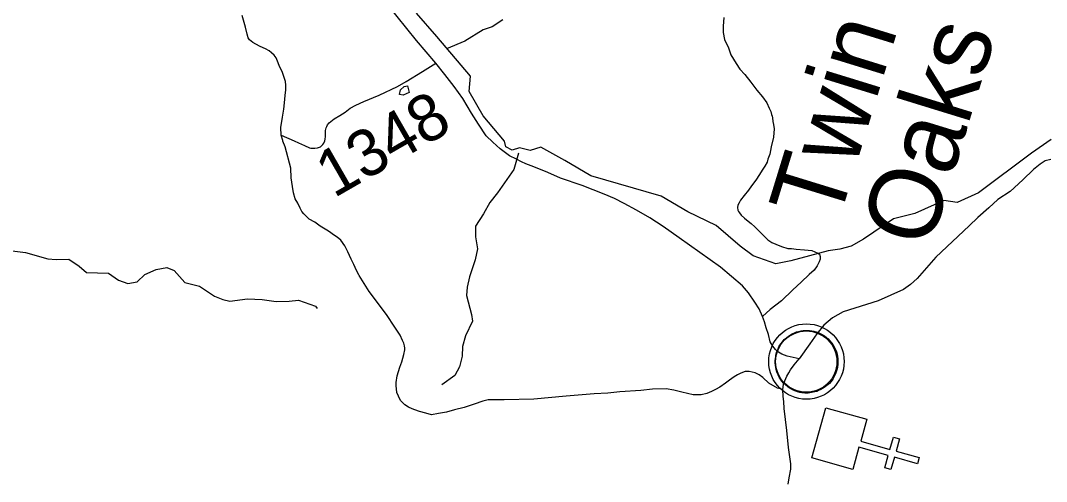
# Model space of a CAD drawing. Extents: x 1347947 to 1350662, y 1027710 to 1030532.
# Drawn here: x 1348247.6 to 1348346.4, y 1029005 to 1029049.4 of the extents above; entities that cross this region are included whole.
import ezdxf

# ---------------------------------------------------------------- set-up
doc = ezdxf.new("R2010")
doc.units = 0
doc.layers.add('Default', color=7, linetype='Continuous')
doc.layers.add('Prop Leader Line Light', color=7, linetype='Continuous')

msp = doc.modelspace()

# ---------------------------------------------------------------- linework, layer by layer
at = {"layer": 'Default'}
for points in [[(1348287.596, 1029045.249), (1348285.737, 1029047.442), (1348282.93, 1029050.893)], [(1348272.718, 1029038.317), (1348272.664, 1029039.067), (1348272.835, 1029040.054), (1348272.962, 1029040.826), (1348273.015, 1029041.423), (1348273.085, 1029042.122), (1348273.143, 1029042.683), (1348273.157, 1029043.125), (1348273.112, 1029043.468), (1348272.84, 1029044.35), (1348272.521, 1029045.015), (1348272.344, 1029045.442), (1348272.213, 1029045.744), (1348272.04, 1029046.009), (1348271.786, 1029046.237), (1348271.543, 1029046.432), (1348271.192, 1029046.629), (1348270.689, 1029046.866), (1348270.253, 1029047.079), (1348269.965, 1029047.242), (1348269.657, 1029047.494), (1348269.539, 1029047.678), (1348269.416, 1029048.026), (1348269.259, 1029048.719), (1348268.952, 1029049.839)], [(1348346.885, 1029037.888), (1348344.993, 1029036.589), (1348339.881, 1029032.765), (1348337.806, 1029031.843), (1348336.544, 1029032.014), (1348333.757, 1029030.782), (1348331.68, 1029030.263), (1348328.8, 1029028.306), (1348327.621, 1029027.63), (1348326.526, 1029027.335), (1348325.385, 1029027.18), (1348321.787, 1029026.211), (1348320.348, 1029025.926), (1348318.162, 1029026.695), (1348316.916, 1029027.631), (1348314.609, 1029029.625), (1348311.88, 1029030.919), (1348309.291, 1029032.455), (1348302.523, 1029034.392), (1348300.036, 1029035.874), (1348297.703, 1029037.164), (1348296.673, 1029036.847), (1348295.653, 1029037.097), (1348294.968, 1029036.872), (1348294.34, 1029037.199), (1348294.219, 1029037.743), (1348292.171, 1029040.162), (1348290.818, 1029042.518), (1348290.93, 1029043.99), (1348287.701, 1029047.804), (1348285.752, 1029050.071)], [(1348294.061, 1029049.412), (1348293.016, 1029048.757), (1348292.153, 1029048.449), (1348290.39, 1029047.373), (1348288.638, 1029046.62)], [(1348315.344, 1029049.632), (1348315.292, 1029048.799), (1348315.269, 1029048.193), (1348315.411, 1029047.533), (1348315.781, 1029046.707), (1348316.028, 1029046.033), (1348316.522, 1029045.213), (1348316.883, 1029044.664), (1348317.363, 1029044.151), (1348317.959, 1029043.409), (1348318.526, 1029042.652), (1348319.064, 1029042.012), (1348319.47, 1029041.424), (1348319.705, 1029040.901), (1348319.859, 1029040.582), (1348319.939, 1029040.289), (1348319.985, 1029040.134), (1348320.033, 1029039.971), (1348320.078, 1029039.629), (1348320.131, 1029039.35), (1348320.179, 1029038.911), (1348320.117, 1029038.135), (1348319.918, 1029037.179), (1348319.767, 1029036.474), (1348319.578, 1029035.996), (1348319.516, 1029035.729), (1348319.296, 1029035.336), (1348319.043, 1029034.956), (1348318.775, 1029034.54), (1348318.433, 1029033.965), (1348318.019, 1029033.45), (1348317.705, 1029033.021), (1348317.309, 1029032.504), (1348316.944, 1029032.058), (1348316.818, 1029031.8), (1348316.705, 1029031.58), (1348316.669, 1029031.342), (1348316.703, 1029031.102), (1348316.761, 1029030.978), (1348316.85, 1029030.825), (1348317.002, 1029030.612), (1348317.326, 1029030.316), (1348317.694, 1029030.024), (1348317.965, 1029029.808), (1348318.338, 1029029.474), (1348318.656, 1029029.159), (1348318.957, 1029028.852), (1348319.287, 1029028.512), (1348319.582, 1029028.246), (1348319.98, 1029027.986), (1348320.367, 1029027.81), (1348320.9, 1029027.584), (1348321.507, 1029027.394), (1348321.848, 1029027.398), (1348322.316, 1029027.345), (1348323.112, 1029027.27), (1348323.813, 1029027.21), (1348324.392, 1029026.96), (1348324.555, 1029026.842), (1348324.612, 1029026.632), (1348324.609, 1029026.365), (1348324.525, 1029026.108), (1348324.337, 1029025.734), (1348324.048, 1029025.309), (1348323.562, 1029024.898), (1348322.778, 1029024.174), (1348321.978, 1029023.414), (1348320.883, 1029022.365), (1348319.821, 1029021.522), (1348319.071, 1029020.842)], [(1348272.718, 1029038.317), (1348273.968, 1029037.778), (1348274.379, 1029037.56), (1348274.935, 1029037.304), (1348275.42, 1029037.09), (1348275.553, 1029037.063), (1348275.711, 1029037.049), (1348275.961, 1029037.064), (1348276.192, 1029037.082), (1348276.314, 1029037.141), (1348276.495, 1029037.203), (1348276.703, 1029037.403), (1348276.813, 1029037.548), (1348276.91, 1029037.765), (1348276.934, 1029037.915), (1348276.965, 1029038.187), (1348276.96, 1029038.529), (1348276.973, 1029038.773), (1348277.034, 1029039.011), (1348277.095, 1029039.148), (1348277.154, 1029039.303), (1348277.337, 1029039.509), (1348277.819, 1029039.892), (1348278.34, 1029040.21), (1348278.861, 1029040.539), (1348279.359, 1029040.916), (1348279.885, 1029041.201), (1348280.657, 1029041.543), (1348282.139, 1029042.17), (1348283.916, 1029042.999), (1348284.756, 1029043.481), (1348286.316, 1029044.436), (1348287.596, 1029045.249)], [(1348319.071, 1029020.842), (1348318.744, 1029021.584), (1348318.321, 1029022.24), (1348317.71, 1029023.142), (1348317.142, 1029023.812), (1348315.021, 1029025.606), (1348311.048, 1029028.418), (1348309.509, 1029029.511), (1348308.226, 1029030.369), (1348306.945, 1029031.093), (1348305.75, 1029031.736), (1348304.797, 1029032.21), (1348303.821, 1029032.645), (1348301.699, 1029033.47), (1348299.614, 1029034.174), (1348298.394, 1029034.713), (1348297.051, 1029035.267), (1348296.276, 1029035.553), (1348295.859, 1029035.759), (1348295.357, 1029036.006), (1348294.7, 1029036.332), (1348293.814, 1029037.007), (1348293.091, 1029037.625), (1348292.457, 1029038.25), (1348291.717, 1029039.383), (1348291.052, 1029040.445), (1348290.186, 1029041.848), (1348289.372, 1029043), (1348288.465, 1029044.163), (1348287.596, 1029045.249)], [(1348285.043, 1029042.412), (1348284.45, 1029042.172), (1348284.103, 1029042.233), (1348284.213, 1029042.663), (1348284.535, 1029042.999), (1348284.859, 1029043.049), (1348285.043, 1029042.412)], [(1348285.043, 1029042.412), (1348284.45, 1029042.172), (1348284.103, 1029042.233), (1348284.213, 1029042.663), (1348284.535, 1029042.999), (1348284.859, 1029043.049), (1348285.043, 1029042.412)], [(1348321.021, 1029013.83), (1348320.503, 1029013.967), (1348319.688, 1029014.434), (1348319.109, 1029014.983), (1348318.751, 1029015.232), (1348318.35, 1029015.429), (1348317.797, 1029015.548), (1348317.413, 1029015.56), (1348316.981, 1029015.402), (1348316.66, 1029015.221), (1348316.329, 1029015.032), (1348315.893, 1029014.713), (1348315.494, 1029014.445), (1348314.946, 1029014.046), (1348314.542, 1029013.818), (1348314.156, 1029013.647), (1348313.697, 1029013.44), (1348313.165, 1029013.319), (1348312.751, 1029013.3), (1348312.393, 1029013.323), (1348311.311, 1029013.557), (1348310.511, 1029013.774), (1348309.801, 1029013.899), (1348308.479, 1029013.849), (1348307.332, 1029013.723), (1348305.337, 1029013.584), (1348304.155, 1029013.471), (1348302.861, 1029013.399), (1348300.155, 1029013.178), (1348297.036, 1029012.897), (1348294.175, 1029012.814), (1348293.083, 1029012.826), (1348292.633, 1029012.82), (1348292.12, 1029012.693), (1348291.307, 1029012.405), (1348290.316, 1029012.078), (1348289.407, 1029011.876), (1348288.644, 1029011.627), (1348287.845, 1029011.498), (1348287.185, 1029011.394), (1348286.64, 1029011.532), (1348286.026, 1029011.701), (1348285.571, 1029011.858), (1348285.307, 1029011.949), (1348284.979, 1029012.114), (1348284.623, 1029012.346), (1348284.232, 1029012.747), (1348284.101, 1029012.955), (1348283.995, 1029013.176), (1348283.853, 1029013.532), (1348283.769, 1029014.209), (1348283.787, 1029014.493), (1348283.878, 1029015.135), (1348284.133, 1029015.982), (1348284.322, 1029016.493), (1348284.516, 1029017.193), (1348284.606, 1029017.629), (1348284.626, 1029017.805), (1348284.596, 1029018.022), (1348284.512, 1029018.273), (1348284.405, 1029018.557), (1348284.168, 1029019.067), (1348283.572, 1029019.927), (1348282.911, 1029020.965), (1348282.08, 1029022.088), (1348281.186, 1029023.263), (1348280.524, 1029024.288), (1348280.21, 1029024.81), (1348280.186, 1029024.853), (1348279.944, 1029025.294), (1348279.716, 1029025.866), (1348279.458, 1029026.374), (1348279.121, 1029027.072), (1348278.843, 1029027.662), (1348278.443, 1029028.209), (1348278.089, 1029028.477), (1348277.848, 1029028.663), (1348277.268, 1029029.078), (1348276.456, 1029029.566), (1348275.95, 1029029.947), (1348275.389, 1029030.237), (1348274.886, 1029030.741), (1348274.693, 1029030.95), (1348274.523, 1029031.287), (1348274.297, 1029031.752), (1348274.065, 1029032.186), (1348273.887, 1029032.759), (1348273.798, 1029033.377), (1348273.679, 1029034.212), (1348273.633, 1029035.14), (1348273.095, 1029037.205), (1348272.878, 1029037.749), (1348272.873, 1029037.792), (1348272.718, 1029038.317)], [(1348295.549, 1029036.593), (1348295.099, 1029035.018), (1348293.537, 1029032.771), (1348292.805, 1029031.845), (1348292.192, 1029030.733), (1348291.406, 1029029.54), (1348291.416, 1029028.518), (1348291.605, 1029027.37), (1348291.4, 1029026.32), (1348290.828, 1029024.685), (1348290.619, 1029023.677), (1348290.546, 1029022.886), (1348291.041, 1029021.04), (1348291.123, 1029020.401), (1348290.469, 1029018.998), (1348290.173, 1029017.98), (1348290.153, 1029017.048), (1348289.894, 1029016.018), (1348289.432, 1029015.16), (1348288.163, 1029014.278)], [(1348346.855, 1029035.975), (1348346.293, 1029035.843), (1348345.804, 1029035.535), (1348345.159, 1029034.992), (1348344.136, 1029034.002), (1348342.938, 1029032.879), (1348341.739, 1029032.13), (1348340.855, 1029031.328), (1348339.798, 1029030.376)], [(1348339.798, 1029030.376), (1348338.973, 1029029.578), (1348335.779, 1029026.566), (1348333.98, 1029024.515), (1348333.315, 1029023.943), (1348332.662, 1029023.454), (1348330.196, 1029022.362), (1348326.822, 1029021.293), (1348325.813, 1029020.731), (1348324.982, 1029020.015), (1348324.295, 1029019.181), (1348323.62, 1029018.206)], [(1348246.283, 1029027.228), (1348248.082, 1029027.005), (1348250.239, 1029026.413), (1348251.03, 1029026.34), (1348252.26, 1029026.358), (1348253.254, 1029025.704), (1348253.957, 1029025.091), (1348256.081, 1029025.041), (1348257.02, 1029024.346), (1348257.929, 1029024.028), (1348258.837, 1029024.178), (1348259.555, 1029024.886), (1348260.646, 1029025.381), (1348261.689, 1029025.566), (1348262.403, 1029025.276), (1348263.433, 1029024.14), (1348264.835, 1029023.772), (1348266.268, 1029022.801), (1348267.072, 1029022.478), (1348267.759, 1029022.34), (1348269.466, 1029022.557), (1348270.866, 1029022.476), (1348272.226, 1029022.285), (1348273.462, 1029022.322), (1348274.371, 1029022.412), (1348276.012, 1029021.856), (1348276.179, 1029021.635)], [(1348322.607, 1029016.789), (1348321.445, 1029017.022), (1348320.936, 1029017.224), (1348320.613, 1029017.426), (1348320.328, 1029017.692), (1348320.058, 1029017.986), (1348319.807, 1029018.41), (1348319.63, 1029019.13), (1348319.431, 1029019.758), (1348319.256, 1029020.351), (1348319.071, 1029020.842)], [(1348323.62, 1029018.206), (1348322.607, 1029016.789)], [(1348321.021, 1029013.83), (1348321.099, 1029014.311), (1348321.214, 1029014.663), (1348321.421, 1029015.108), (1348321.603, 1029015.418), (1348321.766, 1029015.707), (1348322.116, 1029016.196), (1348322.607, 1029016.789)], [(1348321.539, 1029004.7), (1348321.622, 1029005.32), (1348321.789, 1029006.15), (1348321.79, 1029006.678), (1348321.567, 1029008.236), (1348321.399, 1029009.864), (1348321.14, 1029012.001), (1348321.107, 1029012.655), (1348321.049, 1029013.159), (1348321.021, 1029013.83)]]:
    msp.add_lwpolyline(points, dxfattribs=at)
for points in [[(1348321.919, 1029013.823), (1348321.726, 1029013.926), (1348321.507, 1029014.069), (1348321.278, 1029014.262), (1348321.103, 1029014.437), (1348320.933, 1029014.628), (1348320.791, 1029014.826), (1348320.678, 1029015.024), (1348320.564, 1029015.246), (1348320.462, 1029015.503), (1348320.393, 1029015.745), (1348320.346, 1029015.958), (1348320.317, 1029016.172), (1348320.298, 1029016.399), (1348320.298, 1029016.627), (1348320.308, 1029016.799), (1348320.339, 1029016.985), (1348320.361, 1029017.145), (1348320.427, 1029017.381), (1348320.484, 1029017.542), (1348320.561, 1029017.746), (1348320.646, 1029017.917), (1348320.741, 1029018.084), (1348320.852, 1029018.251), (1348320.984, 1029018.417), (1348321.17, 1029018.625), (1348321.373, 1029018.813), (1348321.563, 1029018.956), (1348321.771, 1029019.097), (1348321.925, 1029019.181), (1348322.135, 1029019.279), (1348322.353, 1029019.365), (1348322.557, 1029019.423), (1348322.778, 1029019.478), (1348322.996, 1029019.506), (1348323.204, 1029019.521), (1348323.405, 1029019.518), (1348323.589, 1029019.51), (1348323.823, 1029019.478), (1348324.002, 1029019.445), (1348324.225, 1029019.383), (1348324.435, 1029019.308), (1348324.636, 1029019.219), (1348324.825, 1029019.119), (1348325.031, 1029018.986), (1348325.222, 1029018.847), (1348325.38, 1029018.703), (1348325.562, 1029018.516), (1348325.718, 1029018.333), (1348325.848, 1029018.151), (1348325.972, 1029017.939), (1348326.09, 1029017.687), (1348326.181, 1029017.454), (1348326.248, 1029017.23), (1348326.288, 1029017.042), (1348326.325, 1029016.754), (1348326.339, 1029016.46), (1348326.322, 1029016.225), (1348326.291, 1029015.968), (1348326.255, 1029015.8), (1348326.211, 1029015.633), (1348326.145, 1029015.429), (1348326.078, 1029015.277), (1348325.985, 1029015.08), (1348325.866, 1029014.879), (1348325.764, 1029014.726), (1348325.634, 1029014.56), (1348325.506, 1029014.415), (1348325.378, 1029014.299), (1348325.148, 1029014.098), (1348324.925, 1029013.945), (1348324.702, 1029013.819), (1348324.471, 1029013.713), (1348324.288, 1029013.644), (1348324.1, 1029013.585), (1348323.792, 1029013.52), (1348323.642, 1029013.499), (1348323.474, 1029013.484), (1348323.144, 1029013.487), (1348322.868, 1029013.515), (1348322.671, 1029013.551), (1348322.435, 1029013.614), (1348322.263, 1029013.668), (1348322.033, 1029013.765)], [(1348329.116, 1029010.963), (1348328.528, 1029008.853), (1348331.348, 1029008.06), (1348331.681, 1029009.246), (1348332.273, 1029009.079), (1348331.94, 1029007.894), (1348334.168, 1029007.268), (1348334.001, 1029006.674), (1348331.773, 1029007.3), (1348331.44, 1029006.115), (1348330.848, 1029006.281), (1348331.181, 1029007.467), (1348328.361, 1029008.259), (1348327.757, 1029006.125), (1348323.814, 1029007.233), (1348325.173, 1029012.071)]]:
    msp.add_lwpolyline(points, close=True, dxfattribs=at)
for centre, radius in [((1348323.298, 1029016.515), 3.63), ((1348323.284, 1029016.508), 2.951)]:
    msp.add_circle(centre, radius, dxfattribs=at)

# ---------------------------------------------------------------- texts
at = {"layer": 'Prop Leader Line Light'}
for s, height, rotation, p in [('Twin', 7, 72.88342, (1348326.301, 1029029.618)), ('Oaks', 7, 72.88342, (1348335.16, 1029027.202)), ('1348', 4.5, 29.94376, (1348277.774, 1029032.209))]:
    msp.add_text(s, height=height, rotation=rotation, dxfattribs=at).set_placement(p)

doc.saveas('drawing.dxf')
